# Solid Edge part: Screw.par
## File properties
Title: Screw
Author: Robert a Rhodes jr
Template: Normal.par
Last saved by: TIET
Revision: 11
Application: Solid Edge
Accuracy: 0.99
Material: aluminum
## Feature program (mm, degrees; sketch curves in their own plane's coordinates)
sketch for "unnamed Protrusion 1" plane through (0, 0, 0) normal (0, -1, 0) x-axis (1, 0, 0)
  circle centre (0, 0) radius 12.5
extrude "unnamed Protrusion 1" add finite 25 along +normal
sketch for "ExtrudedProtrusion_2" plane through (0, -25, 0) normal (0, -1, 0) x-axis (1, 0, 0)
  circle centre (0, 0) radius 10
extrude "ExtrudedProtrusion_2" add finite 96 along +normal
sketch for "ExtrudedProtrusion_3" plane through (0, -121, 0) normal (0, -1, 0) x-axis (1, 0, 0)
  circle centre (0, 0) radius 6
extrude "ExtrudedProtrusion_3" add finite 4 along +normal
sketch for "ExtrudedProtrusion_4" plane through (0, -125, 0) normal (0, -1, 0) x-axis (1, 0, 0)
  circle centre (0, 0) radius 4
extrude "ExtrudedProtrusion_4" add finite 6 along +normal
sketch for "unnamed RevolvedProtrusion 1" plane through (0, 0, 0) normal (0, 0, 1) x-axis (1, 0, 0)
  line (0, -131) -> (6, -131)
  line (6, -131) -> (6, -141)
  line (6, -141) -> (0, -143.8522)
  line (0, -143.8522) -> (0, -131)
revolve "unnamed RevolvedProtrusion 1" add full turn 360 deg about sketch line (0, -131) -> (0, -106.3065)
sketch for "ExtrudedCutout_1" plane through (0, 0, 0) normal (1, 0, 0) x-axis (0, 1, 0)
  circle centre (-13, 0) radius 5.5
extrude "ExtrudedCutout_1" cut finite 222.1 symmetric
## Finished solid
Body 1: solid body, 12 faces, 12 edges, 1 vertex.
  Faces by surface: cylinder 6, plane 5, cone 1
  Edges by curve: circle 10, intersection 2
Bounding box of the edges (mm): 25.000 x 141.000 x 25.000, from (-12.5, -141, -12.5) to (12.5, 0, 12.5).
Cylindrical faces by radius (mm): R4 x1, R5.5 x1, R6 x2, R10 x1, R12.5 x1
Conical faces (half-angle, radius in mm at the cone's reference point): 64.5754 deg R6 x1
Planar faces by outward normal: +y 2, -y 3
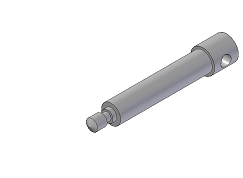
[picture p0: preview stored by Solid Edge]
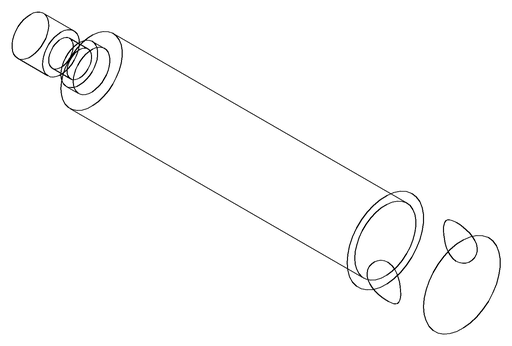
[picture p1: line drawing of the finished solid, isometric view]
